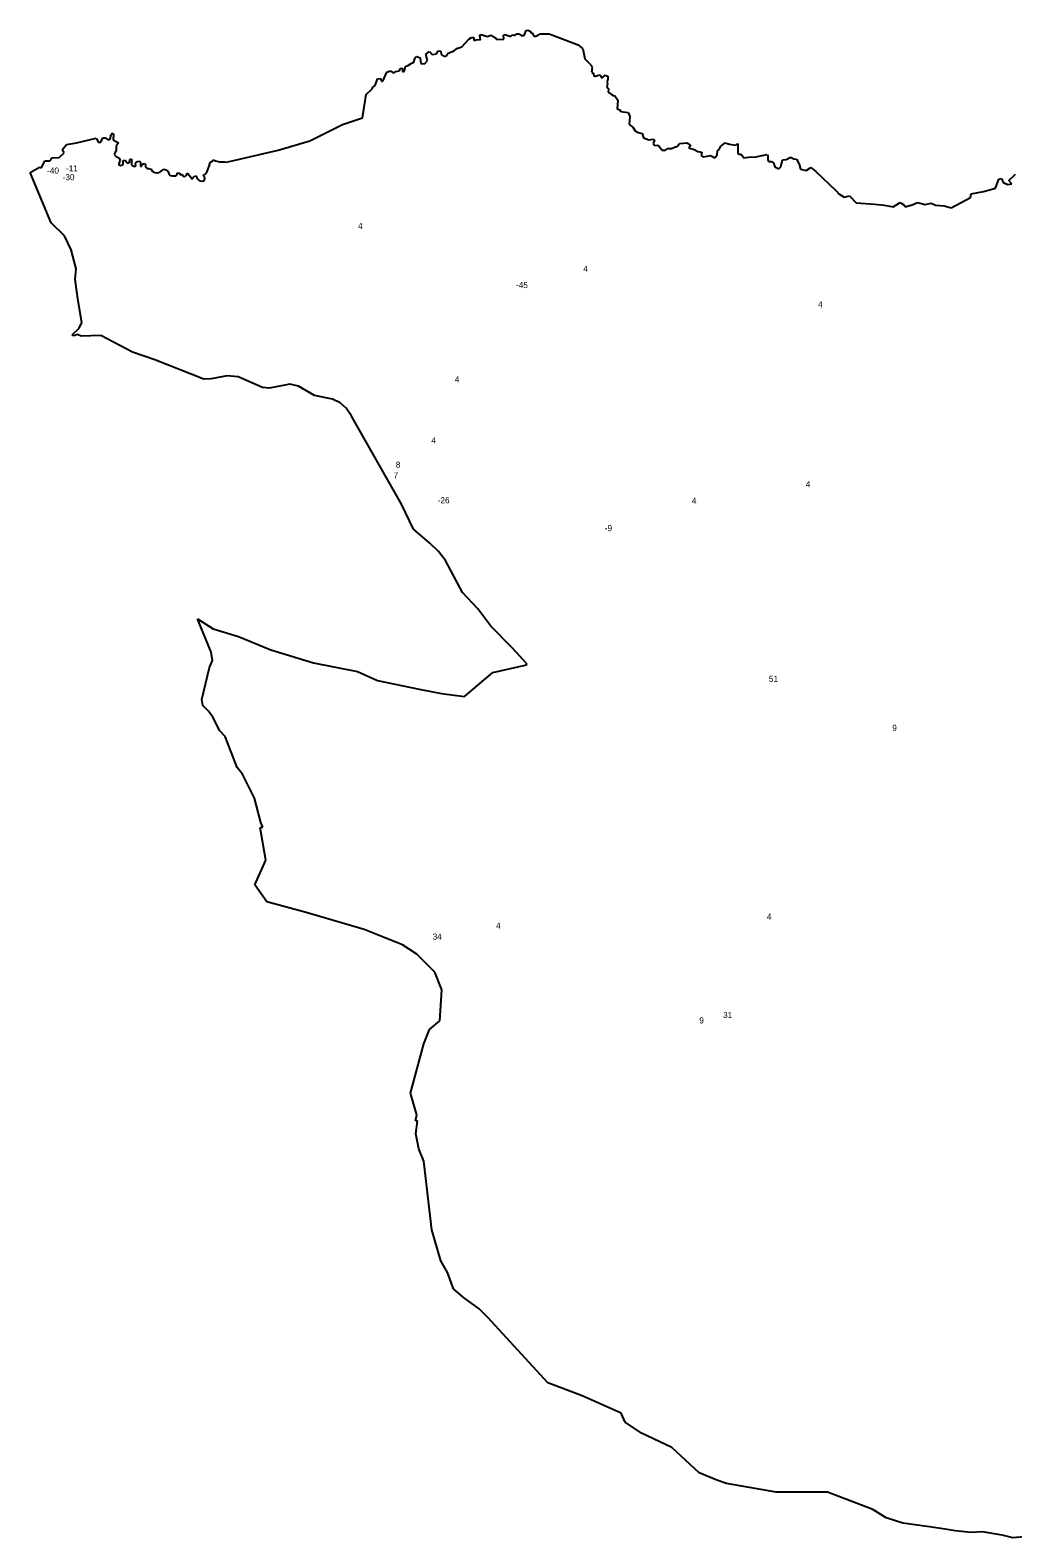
# Model space of a CAD drawing. Extents: x -774899 to -771684, y -969532 to -966391.
# Drawn here: x -774899 to -773293, y -969203 to -966739 of the extents above; entities that cross this region are included whole.
import ezdxf

# ---------------------------------------------------------------- set-up
doc = ezdxf.new("R2010")
doc.units = 0
doc.layers.add('Vrstva 13', color=7, linetype='Continuous')
doc.layers.add('Vrstva 24', color=7, linetype='Continuous')

msp = doc.modelspace()

# ---------------------------------------------------------------- linework, layer by layer
at = {"layer": 'Vrstva 13'}
for p, q in [((-774091.65, -966747.84), (-774088.73, -966739.92)), ((-774088.73, -966739.92), (-774085.6, -966739.29)), ((-774085.6, -966739.29), (-774082.06, -966740.96)), ((-774082.06, -966740.96), (-774080.39, -966743.88)), ((-774080.39, -966743.88), (-774078.51, -966743.67)), ((-774078.51, -966743.67), (-774076.22, -966749.1)), ((-774201.97, -966769.54), (-774193.42, -966766.62)), ((-774193.42, -966766.62), (-774182.37, -966753.9)), ((-774182.37, -966753.9), (-774177.78, -966751.18)), ((-774177.78, -966751.18), (-774174.23, -966751.18)), ((-774174.23, -966751.18), (-774174.03, -966756.19)), ((-774174.03, -966756.19), (-774168.81, -966754.31)), ((-774168.81, -966754.31), (-774163.39, -966754.94)), ((-774164.22, -966747.64), (-774162.35, -966746.59)), ((-774163.39, -966754.94), (-774164.22, -966747.64)), ((-774162.35, -966746.59), (-774151.5, -966749.51)), ((-774151.5, -966749.51), (-774146.08, -966747.22)), ((-774146.08, -966747.22), (-774141.08, -966751.39)), ((-774141.08, -966751.39), (-774139.2, -966750.56)), ((-774139.2, -966750.56), (-774136.28, -966754.31)), ((-774136.28, -966754.31), (-774124.81, -966753.9)), ((-774125.43, -966747.43), (-774122.72, -966746.18)), ((-774124.81, -966753.9), (-774125.43, -966747.43)), ((-774122.72, -966746.18), (-774114.17, -966749.72)), ((-774114.17, -966749.72), (-774110.42, -966746.8)), ((-774110.42, -966746.8), (-774107.29, -966748.05)), ((-774107.29, -966748.05), (-774103.54, -966745.55)), ((-774103.54, -966745.55), (-774100.62, -966745.34)), ((-774100.62, -966745.34), (-774096.65, -966748.05)), ((-774096.65, -966748.05), (-774091.65, -966747.84)), ((-774076.22, -966749.1), (-774072.67, -966749.1)), ((-774072.67, -966749.1), (-774065.58, -966745.14)), ((-774065.58, -966745.14), (-774061.83, -966745.56)), ((-774061.83, -966745.56), (-774051.19, -966745.14)), ((-774051.19, -966745.14), (-774003.43, -966763.5)), ((-774003.43, -966763.5), (-773995.72, -966769.55)), ((-774280.8, -966796.45), (-774274.75, -966792.49)), ((-774274.75, -966792.49), (-774272.66, -966792.49)), ((-774272.66, -966792.49), (-774269.74, -966784.56)), ((-774269.74, -966784.56), (-774267.24, -966782.48)), ((-774267.24, -966782.48), (-774261.61, -966784.35)), ((-774261.61, -966784.35), (-774260.78, -966793.53)), ((-774260.78, -966793.53), (-774254.94, -966794.37)), ((-774254.94, -966794.37), (-774249.72, -966788.73)), ((-774252.23, -966778.3), (-774246.6, -966774.34)), ((-774249.72, -966788.73), (-774252.23, -966778.3)), ((-774246.6, -966774.34), (-774242.01, -966779.14)), ((-774242.01, -966779.14), (-774235.13, -966777.89)), ((-774235.13, -966777.89), (-774232.21, -966772.88)), ((-774232.21, -966772.88), (-774228.04, -966773.5)), ((-774228.04, -966773.5), (-774227.41, -966779.35)), ((-774227.41, -966779.35), (-774222.61, -966782.48)), ((-774222.61, -966782.48), (-774219.28, -966781.43)), ((-774219.28, -966781.43), (-774215.73, -966777.05)), ((-774215.73, -966777.05), (-774206.14, -966773.09)), ((-774206.14, -966773.09), (-774201.97, -966769.54)), ((-773995.72, -966769.55), (-773992.59, -966786.24)), ((-773992.59, -966786.24), (-773986.33, -966792.71)), ((-773986.33, -966792.71), (-773980.91, -966798.96)), ((-774322.72, -966822.53), (-774316.46, -966808.14)), ((-774316.46, -966808.14), (-774312.5, -966806.47)), ((-774312.5, -966806.47), (-774308.95, -966806.05)), ((-774308.95, -966806.05), (-774305.2, -966809.39)), ((-774305.2, -966809.39), (-774301.65, -966806.88)), ((-774301.65, -966806.88), (-774295.4, -966805.84)), ((-774295.4, -966805.84), (-774294.56, -966802.09)), ((-774294.56, -966802.09), (-774291.43, -966801.25)), ((-774291.43, -966801.25), (-774290.39, -966806.68)), ((-774290.39, -966806.68), (-774287.89, -966806.68)), ((-774287.89, -966806.68), (-774285.8, -966798.75)), ((-774285.8, -966798.75), (-774280.8, -966796.45)), ((-773980.91, -966798.96), (-773981.74, -966801.05)), ((-773981.74, -966801.05), (-773980.7, -966802.09)), ((-773980.7, -966802.09), (-773981.74, -966807.73)), ((-773981.74, -966807.73), (-773979.24, -966809.4)), ((-773979.24, -966809.4), (-773977.57, -966814.82)), ((-773977.57, -966814.82), (-773968.19, -966812.11)), ((-773968.19, -966812.11), (-773966.73, -966813.78)), ((-773966.73, -966813.78), (-773966.1, -966817.32)), ((-773966.1, -966817.32), (-773963.6, -966816.91)), ((-773963.6, -966816.91), (-773959.43, -966812.73)), ((-773959.43, -966812.73), (-773955.05, -966814.4)), ((-773955.05, -966814.4), (-773954.84, -966819.62)), ((-774350.24, -966844.44), (-774340.44, -966835.26)), ((-774340.44, -966835.26), (-774339.19, -966832.34)), ((-774339.19, -966832.34), (-774335.44, -966829.62)), ((-774335.44, -966829.62), (-774331.68, -966818.78)), ((-774331.68, -966818.78), (-774326.68, -966818.36)), ((-774326.68, -966818.36), (-774325.01, -966822.74)), ((-774325.01, -966822.74), (-774322.72, -966822.53)), ((-773954.84, -966819.62), (-773956.51, -966824.63)), ((-773956.51, -966824.63), (-773955.68, -966825.88)), ((-773955.68, -966825.88), (-773956.5, -966833.18)), ((-773956.5, -966833.18), (-773954.21, -966835.06)), ((-773954.21, -966835.06), (-773954.62, -966840.69)), ((-773954.62, -966840.69), (-773949.2, -966844.45)), ((-774355.87, -966882.4), (-774350.24, -966844.44)), ((-773949.2, -966844.45), (-773946.49, -966846.32)), ((-773946.49, -966846.32), (-773943.57, -966846.53)), ((-773943.57, -966846.53), (-773938.78, -966853.83)), ((-773938.78, -966853.83), (-773939.61, -966867.81)), ((-774388.61, -966893.46), (-774355.87, -966882.4)), ((-773939.61, -966867.81), (-773935.65, -966869.48)), ((-773935.65, -966869.48), (-773933.98, -966872.4)), ((-773933.98, -966872.4), (-773921.88, -966873.86)), ((-773921.88, -966873.86), (-773919.38, -966880.33)), ((-773919.38, -966880.33), (-773920.21, -966893.68)), ((-774823.53, -966923.39), (-774791, -966915.88)), ((-774791, -966915.88), (-774787.24, -966922.97)), ((-774783.49, -966922.14), (-774780.15, -966915.04)), ((-774780.15, -966915.04), (-774775.98, -966915.04)), ((-774775.98, -966915.04), (-774772.23, -966918.8)), ((-774767.64, -966917.13), (-774767.22, -966910.87)), ((-774767.22, -966910.87), (-774765.14, -966907.53)), ((-774765.14, -966907.53), (-774762.63, -966909.2)), ((-774762.63, -966909.2), (-774763.47, -966918.38)), ((-774442, -966920.16), (-774388.61, -966893.46)), ((-773920.21, -966893.68), (-773914.38, -966898.06)), ((-773914.38, -966898.06), (-773910.41, -966903.9)), ((-773910.41, -966903.9), (-773905.62, -966906.82)), ((-773905.62, -966906.82), (-773898.94, -966908.08)), ((-773898.94, -966908.08), (-773897.07, -966915.17)), ((-773897.07, -966915.17), (-773888.1, -966918.51)), ((-774851.89, -966947.17), (-774843.55, -966939.66)), ((-774846.89, -966934.66), (-774839.38, -966926.31)), ((-774843.55, -966939.66), (-774846.89, -966934.66)), ((-774839.38, -966926.31), (-774823.53, -966923.39)), ((-774787.24, -966922.97), (-774783.49, -966922.14)), ((-774772.23, -966918.8), (-774767.64, -966917.13)), ((-774763.47, -966918.38), (-774754.71, -966923.39)), ((-774758.46, -966935.49), (-774761.7, -966942.27)), ((-774754.71, -966923.39), (-774758.46, -966928.81)), ((-774758.46, -966928.81), (-774758.46, -966935.49)), ((-774564.2, -966951.67), (-774493.92, -966935.19)), ((-774493.92, -966935.19), (-774442, -966920.16)), ((-773888.1, -966918.51), (-773881.42, -966917.26)), ((-773881.42, -966917.26), (-773878.93, -966918.3)), ((-773878.93, -966918.3), (-773880.8, -966924.35)), ((-773880.8, -966924.35), (-773878.09, -966927.69)), ((-773878.09, -966927.69), (-773872.67, -966927.27)), ((-773872.67, -966927.27), (-773866.2, -966935.41)), ((-773866.2, -966935.41), (-773860.78, -966935.61)), ((-773860.78, -966935.61), (-773858.28, -966932.49)), ((-773858.28, -966932.49), (-773851.19, -966932.9)), ((-773851.19, -966932.9), (-773845.98, -966930.4)), ((-773845.98, -966930.4), (-773841.18, -966928.73)), ((-773841.18, -966928.73), (-773837.84, -966924.56)), ((-773837.84, -966924.56), (-773831.59, -966923.93)), ((-773831.59, -966923.93), (-773826.17, -966923.3)), ((-773826.17, -966923.3), (-773820.12, -966926.85)), ((-773820.12, -966926.85), (-773822.62, -966931.86)), ((-773822.62, -966931.86), (-773813.86, -966934.57)), ((-773813.86, -966934.57), (-773808.23, -966937.49)), ((-773808.23, -966937.49), (-773801.56, -966938.74)), ((-773801.56, -966938.74), (-773802.39, -966943.96)), ((-773776.53, -966942.91), (-773776.12, -966936.66)), ((-773776.12, -966936.66), (-773773.2, -966934.36)), ((-773773.2, -966934.36), (-773770.49, -966929.14)), ((-773770.49, -966929.14), (-773763.4, -966923.72)), ((-773763.4, -966923.72), (-773756.51, -966925.81)), ((-773756.51, -966925.81), (-773746.09, -966927.06)), ((-773746.09, -966927.06), (-773743.37, -966924.35)), ((-773743.37, -966924.35), (-773742.54, -966926.43)), ((-773742.54, -966926.43), (-773742.54, -966941.04)), ((-773742.54, -966941.04), (-773740.66, -966942.08)), ((-774899.02, -966971.79), (-774883.59, -966963.45)), ((-774883.59, -966963.45), (-774880.25, -966964.28)), ((-774880.25, -966964.28), (-774875.25, -966953.01)), ((-774875.25, -966953.01), (-774866.91, -966953.01)), ((-774866.91, -966953.01), (-774864.82, -966950.93)), ((-774864.82, -966950.93), (-774864.4, -966948.01)), ((-774864.4, -966948.01), (-774851.89, -966947.17)), ((-774761.7, -966942.27), (-774758.36, -966945.82)), ((-774758.36, -966945.82), (-774754.19, -966948.11)), ((-774752.1, -966951.87), (-774754.61, -966958.75)), ((-774754.61, -966958.75), (-774751.48, -966960.63)), ((-774754.19, -966948.11), (-774752.1, -966951.87)), ((-774751.48, -966960.63), (-774747.1, -966958.75)), ((-774747.1, -966958.75), (-774746.89, -966952.08)), ((-774746.89, -966952.08), (-774743.76, -966951.87)), ((-774743.76, -966951.87), (-774741.88, -966955)), ((-774741.88, -966955), (-774740.01, -966956.88)), ((-774740.01, -966956.88), (-774736.88, -966955)), ((-774736.88, -966955), (-774736.25, -966950.83)), ((-774736.25, -966950.83), (-774733.75, -966949.78)), ((-774733.75, -966949.78), (-774732.71, -966953.12)), ((-774732.71, -966953.12), (-774733.75, -966956.67)), ((-774733.75, -966956.67), (-774733.13, -966959.8)), ((-774733.13, -966959.8), (-774728.33, -966962.3)), ((-774728.33, -966962.3), (-774726.45, -966960.84)), ((-774726.66, -966956.46), (-774723.74, -966953.96)), ((-774726.45, -966960.84), (-774726.66, -966956.46)), ((-774723.74, -966953.96), (-774720.2, -966953.54)), ((-774720.2, -966953.54), (-774718.74, -966955)), ((-774718.74, -966955), (-774718.74, -966959.8)), ((-774718.74, -966959.8), (-774718.53, -966961.88)), ((-774718.53, -966961.88), (-774716.86, -966961.67)), ((-774716.86, -966961.67), (-774715.82, -966958.96)), ((-774715.82, -966958.96), (-774712.9, -966957.29)), ((-774712.9, -966957.29), (-774710.81, -966958.75)), ((-774710.81, -966958.75), (-774710.6, -966961.05)), ((-774710.6, -966961.05), (-774710.39, -966963.34)), ((-774710.39, -966963.34), (-774708.1, -966965.22)), ((-774708.1, -966965.22), (-774705.6, -966965.43)), ((-774705.6, -966965.43), (-774701.43, -966966.47)), ((-774609.66, -966970.23), (-774606.54, -966961.68)), ((-774606.54, -966961.68), (-774605.08, -966955.63)), ((-774605.08, -966955.63), (-774602.36, -966953.96)), ((-774602.36, -966953.96), (-774599.86, -966951.25)), ((-774599.86, -966951.25), (-774596.11, -966953.13)), ((-774596.11, -966953.13), (-774589.43, -966954.59)), ((-774589.43, -966954.59), (-774581.51, -966954.38)), ((-774581.51, -966954.38), (-774578.59, -966955.21)), ((-774578.59, -966955.21), (-774564.2, -966951.67)), ((-773802.39, -966943.96), (-773798.22, -966946.46)), ((-773798.22, -966946.46), (-773787.59, -966943.96)), ((-773787.59, -966943.96), (-773780.5, -966947.71)), ((-773780.5, -966947.71), (-773776.53, -966942.91)), ((-773740.66, -966942.08), (-773737.33, -966942.08)), ((-773737.33, -966942.08), (-773732.95, -966947.92)), ((-773732.95, -966947.92), (-773721.48, -966946.46)), ((-773721.48, -966946.46), (-773716.06, -966947.09)), ((-773716.06, -966947.09), (-773694.78, -966942.71)), ((-773694.78, -966942.71), (-773693.53, -966944.79)), ((-773693.53, -966944.79), (-773693.74, -966950.84)), ((-773693.74, -966950.84), (-773692.48, -966953.76)), ((-773692.48, -966953.76), (-773687.9, -966953.76)), ((-773687.9, -966953.76), (-773684.56, -966956.06)), ((-773684.56, -966956.06), (-773682.06, -966962.94)), ((-773682.06, -966962.94), (-773675.59, -966966.07)), ((-773675.59, -966966.07), (-773672.46, -966962.52)), ((-773672.46, -966962.52), (-773669.96, -966951.47)), ((-773669.96, -966951.47), (-773663.7, -966950.63)), ((-773663.7, -966950.63), (-773656.61, -966946.88)), ((-773656.61, -966946.88), (-773650.98, -966949.59)), ((-773650.98, -966949.59), (-773646.81, -966950.21)), ((-773646.81, -966950.21), (-773642.43, -966958.56)), ((-773642.43, -966958.56), (-773640.14, -966966.7)), ((-773631.17, -966968.57), (-773623.25, -966963.98)), ((-773623.25, -966963.98), (-773615.11, -966970.45)), ((-774864.78, -967054.14), (-774899.02, -966971.79)), ((-774701.43, -966966.47), (-774699.97, -966969.39)), ((-774699.97, -966969.39), (-774695.38, -966971.69)), ((-774695.38, -966971.69), (-774690.79, -966972.31)), ((-774690.79, -966972.31), (-774687.24, -966971.27)), ((-774687.24, -966971.27), (-774680.78, -966966.47)), ((-774680.78, -966966.47), (-774677.23, -966967.31)), ((-774677.23, -966967.31), (-774674.32, -966969.6)), ((-774674.32, -966969.6), (-774672.44, -966973.36)), ((-774672.44, -966973.36), (-774670.35, -966976.7)), ((-774670.35, -966976.7), (-774666.18, -966977.53)), ((-774666.18, -966977.53), (-774661.18, -966977.53)), ((-774661.18, -966977.53), (-774659.3, -966975.03)), ((-774659.3, -966975.03), (-774657.63, -966972.73)), ((-774657.63, -966972.73), (-774654.29, -966972.94)), ((-774654.29, -966972.94), (-774654.29, -966975.03)), ((-774654.29, -966975.03), (-774650.54, -966975.44)), ((-774650.54, -966975.44), (-774649.71, -966978.16)), ((-774649.71, -966978.16), (-774646.37, -966978.36)), ((-774646.37, -966978.36), (-774642.82, -966976.49)), ((-774642.82, -966976.49), (-774643.24, -966972.94)), ((-774643.24, -966972.94), (-774640.32, -966974.61)), ((-774640.32, -966974.61), (-774637.61, -966978.58)), ((-774637.61, -966978.58), (-774636.15, -966981.5)), ((-774636.15, -966981.5), (-774633.23, -966981.5)), ((-774633.23, -966981.5), (-774631.98, -966979.62)), ((-774631.98, -966979.62), (-774629.68, -966977.54)), ((-774629.68, -966977.54), (-774628.02, -966977.75)), ((-774628.02, -966977.75), (-774626.97, -966979.83)), ((-774626.97, -966979.83), (-774625.1, -966983.59)), ((-774625.1, -966983.59), (-774621.97, -966985.46)), ((-774621.97, -966985.46), (-774617.17, -966985.88)), ((-774617.17, -966985.88), (-774614.88, -966985.67)), ((-774615.92, -966977.95), (-774615.5, -966976.08)), ((-774613.21, -966980.04), (-774615.92, -966977.95)), ((-774615.5, -966976.08), (-774612.79, -966974.62)), ((-774614.88, -966985.67), (-774613.21, -966980.04)), ((-774612.79, -966974.62), (-774609.66, -966970.23)), ((-773640.14, -966966.7), (-773631.17, -966968.57)), ((-773615.11, -966970.45), (-773581.75, -967002.16)), ((-773321.69, -966997.78), (-773316.26, -966982.97)), ((-773316.26, -966982.97), (-773312.09, -966981.51)), ((-773312.09, -966981.51), (-773308.97, -966988.19)), ((-773308.97, -966988.19), (-773301.67, -966991.53)), ((-773300, -966985.27), (-773288.94, -966974.84)), ((-773295.2, -966990.69), (-773300, -966985.27)), ((-773581.75, -967002.16), (-773577.78, -967006.54)), ((-773577.78, -967006.54), (-773569.02, -967012.18)), ((-773569.02, -967012.18), (-773560.47, -967010.3)), ((-773560.47, -967010.3), (-773549.42, -967021.56)), ((-773394.05, -967029.49), (-773362.56, -967013.01)), ((-773362.56, -967013.01), (-773361.52, -967006.96)), ((-773361.52, -967006.96), (-773341.5, -967002.79)), ((-773341.5, -967002.79), (-773321.69, -966997.78)), ((-773301.67, -966991.53), (-773295.2, -966990.69)), ((-773549.42, -967021.56), (-773518.76, -967023.44)), ((-773518.76, -967023.44), (-773503.54, -967025.11)), ((-773503.54, -967025.11), (-773488.94, -967028.03)), ((-773488.94, -967028.03), (-773477.26, -967020.94)), ((-773477.26, -967020.94), (-773471.63, -967024.9)), ((-773471.63, -967024.9), (-773469.75, -967027.82)), ((-773469.75, -967027.82), (-773458.08, -967024.9)), ((-773458.08, -967024.9), (-773449.11, -967020.73)), ((-773449.11, -967020.73), (-773436.39, -967024.27)), ((-773436.39, -967024.27), (-773426.79, -967021.98)), ((-773426.79, -967021.98), (-773419.91, -967025.53)), ((-773419.91, -967025.53), (-773405.73, -967026.16)), ((-773405.73, -967026.16), (-773394.05, -967029.49)), ((-774843.11, -967075.23), (-774864.78, -967054.14)), ((-774831.99, -967098.08), (-774843.11, -967075.23)), ((-774823.79, -967129.13), (-774831.99, -967098.08)), ((-774825.54, -967146.12), (-774823.79, -967129.13)), ((-774821.22, -967178.56), (-774825.54, -967146.12)), ((-774814.49, -967216.93), (-774821.22, -967178.56)), ((-774830.3, -967237.14), (-774819.17, -967226.45)), ((-774821.5, -967236.91), (-774827.54, -967239.1)), ((-774815.51, -967239.42), (-774821.5, -967236.91)), ((-774819.17, -967226.45), (-774814.49, -967216.93)), ((-774827.54, -967239.1), (-774830.3, -967237.14)), ((-774783.31, -967238.2), (-774815.51, -967239.42)), ((-774731.88, -967265.6), (-774783.31, -967238.2)), ((-774695.24, -967278.3), (-774731.88, -967265.6)), ((-774615.06, -967309.47), (-774695.24, -967278.3)), ((-774603.25, -967309.3), (-774615.06, -967309.47)), ((-774576.98, -967304.18), (-774603.25, -967309.3)), ((-774559.1, -967306.01), (-774576.98, -967304.18)), ((-774519.32, -967323.33), (-774559.1, -967306.01)), ((-774507.78, -967324.22), (-774519.32, -967323.33)), ((-774474.91, -967317.78), (-774507.78, -967324.22)), ((-774460.68, -967321.16), (-774474.91, -967317.78)), ((-774434.44, -967336.26), (-774460.68, -967321.16)), ((-774405.12, -967342.49), (-774434.44, -967336.26)), ((-774392.6, -967348.62), (-774405.12, -967342.49)), ((-774382.7, -967356.83), (-774392.6, -967348.62)), ((-774374.37, -967369.19), (-774382.7, -967356.83)), ((-774292.04, -967513.75), (-774374.37, -967369.19)), ((-774272.38, -967554.98), (-774292.04, -967513.75)), ((-774245.77, -967577.64), (-774272.38, -967554.98)), ((-774231.77, -967591.58), (-774245.77, -967577.64)), ((-774220.16, -967606.01), (-774231.77, -967591.58)), ((-774192.7, -967658.42), (-774220.16, -967606.01)), ((-774167.35, -967685.2), (-774192.7, -967658.42)), ((-774603.38, -967755.65), (-774625.4, -967701.51)), ((-774625.4, -967701.51), (-774599.79, -967717.85)), ((-774146.55, -967713.34), (-774167.35, -967685.2)), ((-774599.79, -967717.85), (-774558.75, -967730.24)), ((-774111.2, -967748.54), (-774146.55, -967713.34)), ((-774558.75, -967730.24), (-774505.66, -967752.26)), ((-774505.66, -967752.26), (-774436, -967773.19)), ((-774086.68, -967775.52), (-774111.2, -967748.54)), ((-774606.2, -967780.77), (-774600.95, -967769.33)), ((-774600.95, -967769.33), (-774603.38, -967755.65)), ((-774436, -967773.19), (-774364.28, -967787.48)), ((-774142.86, -967789.17), (-774090.33, -967777.26)), ((-774090.33, -967777.26), (-774086.68, -967775.52)), ((-774618.58, -967833), (-774606.2, -967780.77)), ((-774364.28, -967787.48), (-774331.46, -967801.95)), ((-774331.46, -967801.95), (-774263.63, -967816.55)), ((-774189.51, -967828.1), (-774142.86, -967789.17)), ((-774263.63, -967816.55), (-774226.93, -967823.61)), ((-774226.93, -967823.61), (-774189.51, -967828.1)), ((-774616.97, -967842.92), (-774618.58, -967833)), ((-774607.35, -967852.48), (-774616.97, -967842.92)), ((-774600.74, -967862.25), (-774607.35, -967852.48)), ((-774589.33, -967884.52), (-774600.74, -967862.25)), ((-774580.63, -967893.72), (-774589.33, -967884.52)), ((-774560.92, -967944.24), (-774580.63, -967893.72)), ((-774552.26, -967955.53), (-774560.92, -967944.24)), ((-774532.22, -967994.28), (-774552.26, -967955.53)), ((-774522.05, -968034.24), (-774532.22, -967994.28)), ((-774523, -968042.54), (-774519.01, -968041.82)), ((-774513.84, -968095.91), (-774523, -968042.54)), ((-774519.01, -968041.82), (-774522.05, -968034.24)), ((-774532.17, -968136.03), (-774513.84, -968095.91)), ((-774512.08, -968164.19), (-774532.17, -968136.03)), ((-774448.25, -968181.58), (-774512.08, -968164.19)), ((-774353.13, -968208.93), (-774448.25, -968181.58)), ((-774290.43, -968234.34), (-774353.13, -968208.93)), ((-774267.27, -968249.4), (-774290.43, -968234.34)), ((-774238.04, -968278.74), (-774267.27, -968249.4)), ((-774226.52, -968307.56), (-774238.04, -968278.74)), ((-774229.6, -968358.4), (-774226.52, -968307.56)), ((-774246.51, -968372.45), (-774229.6, -968358.4)), ((-774255.92, -968396.27), (-774246.51, -968372.45)), ((-774277.72, -968476.38), (-774255.92, -968396.27)), ((-774267.38, -968511.87), (-774277.72, -968476.38)), ((-774269.34, -968521.28), (-774267.38, -968511.87)), ((-774266.09, -968522.51), (-774269.34, -968521.28)), ((-774268.98, -968543.04), (-774266.09, -968522.51)), ((-774263.8, -968567.4), (-774268.98, -968543.04)), ((-774255.58, -968587.5), (-774263.8, -968567.4)), ((-774242.82, -968700.26), (-774255.58, -968587.5)), ((-774227.99, -968750.49), (-774242.82, -968700.26)), ((-774216.84, -968769.68), (-774227.99, -968750.49)), ((-774207.15, -968796.66), (-774216.84, -968769.68)), ((-774191.59, -968809.94), (-774207.15, -968796.66)), ((-774165.23, -968829.25), (-774191.59, -968809.94)), ((-774150.92, -968843.22), (-774165.23, -968829.25)), ((-774053.05, -968950.13), (-774150.92, -968843.22)), ((-773997.22, -968971.14), (-774053.05, -968950.13)), ((-773933.25, -968999.59), (-773997.22, -968971.14)), ((-773926.96, -969014.43), (-773933.25, -968999.59)), ((-773900.1, -969032.45), (-773926.96, -969014.43)), ((-773850.63, -969055.54), (-773900.1, -969032.45)), ((-773806.02, -969097.33), (-773850.63, -969055.54)), ((-773776.97, -969109.4), (-773806.02, -969097.33)), ((-773761.23, -969114.43), (-773776.97, -969109.4)), ((-773680.29, -969128.6), (-773761.23, -969114.43)), ((-773595.92, -969128.77), (-773680.29, -969128.6)), ((-773522.04, -969157.22), (-773595.92, -969128.77)), ((-773500.43, -969170.54), (-773522.04, -969157.22)), ((-773473.06, -969179.57), (-773500.43, -969170.54)), ((-773429.47, -969185.27), (-773473.06, -969179.57)), ((-773403.73, -969189.34), (-773429.47, -969185.27)), ((-773387.37, -969191.85), (-773403.73, -969189.34)), ((-773361.31, -969194.42), (-773387.37, -969191.85)), ((-773342.9, -969193.46), (-773361.31, -969194.42)), ((-773310.91, -969198.83), (-773342.9, -969193.46)), ((-773293.46, -969203.4), (-773310.91, -969198.83)), ((-773274.63, -969201.98), (-773293.46, -969203.4))]:
    msp.add_line(p, q, dxfattribs=at)

# ---------------------------------------------------------------- texts
at = {"layer": 'Vrstva 24'}
for s, p in [('-40', (-774871.316, -966973.75)), ('-11', (-774840.419, -966970.25)), ('-30', (-774845.86, -966984.62)), ('4', (-774363.322, -967064.28)), ('4', (-773995.232, -967134.17)), ('-45', (-774105.166, -967160.9)), ('4', (-773611.502, -967192.58)), ('4', (-774205.232, -967315.03)), ('4', (-774243.602, -967414.75)), ('8', (-774301.516, -967454.55)), ('7', (-774305.176, -967471.7)), ('4', (-773631.742, -967486.53)), ('-26', (-774233.054, -967512.54)), ('4', (-773817.762, -967513.23)), ('-9', (-773960.084, -967558.19)), ('51', (-773691.921, -967804.49)), ('9', (-773490.26, -967884.56)), ('4', (-774137.672, -968207.95)), ('4', (-773695.132, -968192.93)), ('34', (-774241.322, -968225.79)), ('31', (-773766.751, -968353.82)), ('9', (-773805.6, -968362.72))]:
    msp.add_text(s, height=10, dxfattribs=at).set_placement(p)

doc.saveas('drawing.dxf')
